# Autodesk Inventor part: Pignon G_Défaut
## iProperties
Shininess: 64.0
Length Units: 11269
Angle Units: 11279
Time Units: 11290
Mass Units: 11283
Length Display Precision: 3
Angle Display Precision: 2
Compacted: True
Part Number: Pignon G_Défaut
Document SubType Name: Modeling
Created: 2006-01
Material: Par défaut
Designer: Fricot
Density: 0.0
Volumn: 0.0
Area: 0.0
PropertySet Name: Model Information
Control State: 0
Master: False
Checked Out: False
Author: Fricot
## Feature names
1. Base1
